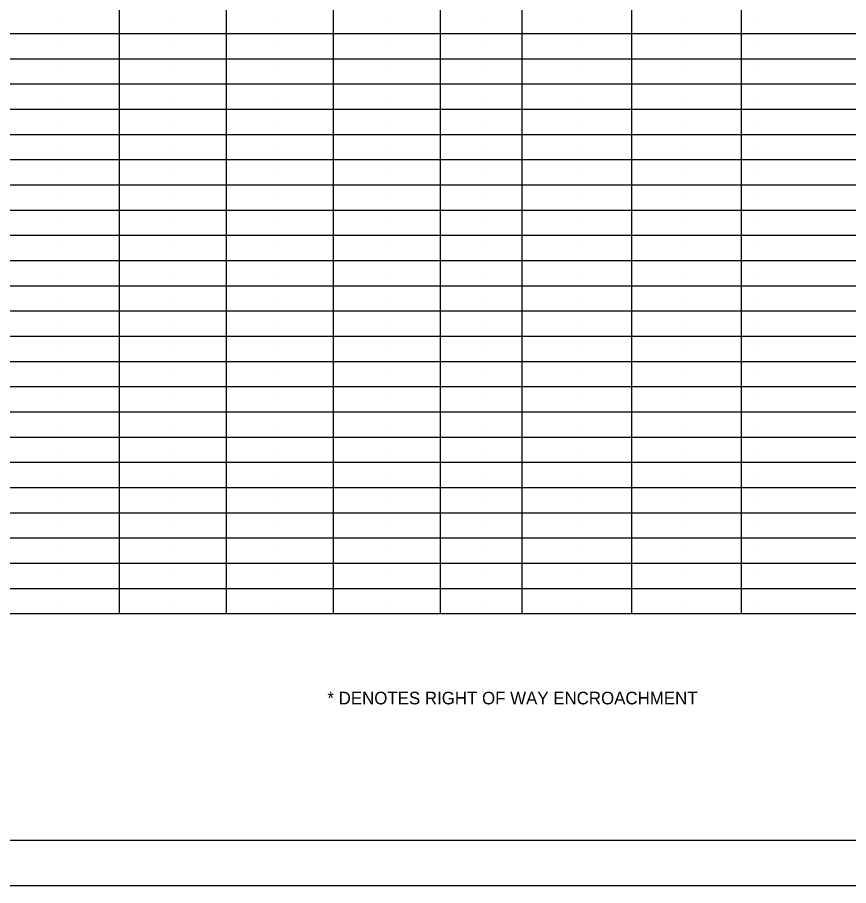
# Model space of a CAD drawing. Extents: x 0 to 34, y 0 to 22.
# Drawn here: x 15.55 to 24.77, y 0 to 9.64 of the extents above; entities that cross this region are included whole.
import ezdxf

# ---------------------------------------------------------------- set-up
doc = ezdxf.new("R2010")
doc.units = 0
for name, color, linetype in [('SC_Scratch1', 7, 'Continuous'), ('SH_Border', 7, 'Continuous'), ('SH_Cut_Line', 7, 'Continuous'), ('SH_Data', 7, 'Continuous')]:
    doc.layers.add(name, color=color, linetype=linetype)

msp = doc.modelspace()

# ---------------------------------------------------------------- linework, layer by layer
at = {"layer": 'SC_Scratch1'}
for p, q in [((16.0519, 9.6), (16.0519, 9.6)), ((17.2706, 9.6), (17.2706, 9.6)), ((18.4581, 9.6), (18.4581, 9.6)), ((19.6456, 9.6), (19.6456, 9.6)), ((20.6925, 9.6), (20.6925, 9.6)), ((21.7549, 9.6), (21.7549, 9.6)), ((22.9737, 9.6), (22.9737, 9.6)), ((23.723, 9.6), (23.723, 9.6)), ((16.0519, 9.32), (16.0519, 9.32)), ((17.2706, 9.32), (17.2706, 9.32)), ((18.4581, 9.32), (18.4581, 9.32)), ((19.6456, 9.32), (19.6456, 9.32)), ((20.6925, 9.32), (20.6925, 9.32)), ((21.7549, 9.32), (21.7549, 9.32)), ((22.9737, 9.32), (22.9737, 9.32)), ((23.723, 9.32), (23.723, 9.32)), ((16.0519, 9.04), (16.0519, 9.04)), ((17.2706, 9.04), (17.2706, 9.04)), ((18.4581, 9.04), (18.4581, 9.04)), ((19.6456, 9.04), (19.6456, 9.04)), ((20.6925, 9.04), (20.6925, 9.04)), ((21.7549, 9.04), (21.7549, 9.04)), ((22.9737, 9.04), (22.9737, 9.04)), ((23.723, 9.04), (23.723, 9.04)), ((16.0519, 8.76), (16.0519, 8.76)), ((17.2706, 8.76), (17.2706, 8.76)), ((18.4581, 8.76), (18.4581, 8.76)), ((19.6456, 8.76), (19.6456, 8.76)), ((20.6925, 8.76), (20.6925, 8.76)), ((21.7549, 8.76), (21.7549, 8.76)), ((22.9737, 8.76), (22.9737, 8.76)), ((23.723, 8.76), (23.723, 8.76)), ((16.0519, 8.48), (16.0519, 8.48)), ((17.2706, 8.48), (17.2706, 8.48)), ((18.4581, 8.48), (18.4581, 8.48)), ((19.6456, 8.48), (19.6456, 8.48)), ((20.6925, 8.48), (20.6925, 8.48)), ((21.7549, 8.48), (21.7549, 8.48)), ((22.9737, 8.48), (22.9737, 8.48)), ((23.723, 8.48), (23.723, 8.48)), ((16.0519, 8.2), (16.0519, 8.2)), ((17.2706, 8.2), (17.2706, 8.2)), ((18.4581, 8.2), (18.4581, 8.2)), ((19.6456, 8.2), (19.6456, 8.2)), ((20.6925, 8.2), (20.6925, 8.2)), ((21.7549, 8.2), (21.7549, 8.2)), ((22.9737, 8.2), (22.9737, 8.2)), ((23.723, 8.2), (23.723, 8.2)), ((16.0519, 7.92), (16.0519, 7.92)), ((17.2706, 7.92), (17.2706, 7.92)), ((18.4581, 7.92), (18.4581, 7.92)), ((19.6456, 7.92), (19.6456, 7.92)), ((20.6925, 7.92), (20.6925, 7.92)), ((21.7549, 7.92), (21.7549, 7.92)), ((22.9737, 7.92), (22.9737, 7.92)), ((23.723, 7.92), (23.723, 7.92)), ((16.0519, 7.64), (16.0519, 7.64)), ((17.2706, 7.64), (17.2706, 7.64)), ((18.4581, 7.64), (18.4581, 7.64)), ((19.6456, 7.64), (19.6456, 7.64)), ((20.6925, 7.64), (20.6925, 7.64)), ((21.7549, 7.64), (21.7549, 7.64)), ((22.9737, 7.64), (22.9737, 7.64)), ((23.723, 7.64), (23.723, 7.64)), ((16.0519, 7.36), (16.0519, 7.36)), ((17.2706, 7.36), (17.2706, 7.36)), ((18.4581, 7.36), (18.4581, 7.36)), ((19.6456, 7.36), (19.6456, 7.36)), ((20.6925, 7.36), (20.6925, 7.36)), ((21.7549, 7.36), (21.7549, 7.36)), ((22.9737, 7.36), (22.9737, 7.36)), ((23.723, 7.36), (23.723, 7.36)), ((16.0519, 7.08), (16.0519, 7.08)), ((17.2706, 7.08), (17.2706, 7.08)), ((18.4581, 7.08), (18.4581, 7.08)), ((19.6456, 7.08), (19.6456, 7.08)), ((20.6925, 7.08), (20.6925, 7.08)), ((21.7549, 7.08), (21.7549, 7.08)), ((22.9737, 7.08), (22.9737, 7.08)), ((23.723, 7.08), (23.723, 7.08)), ((16.0519, 6.8), (16.0519, 6.8)), ((17.2706, 6.8), (17.2706, 6.8)), ((18.4581, 6.8), (18.4581, 6.8)), ((19.6456, 6.8), (19.6456, 6.8)), ((20.6925, 6.8), (20.6925, 6.8)), ((21.7549, 6.8), (21.7549, 6.8)), ((22.9737, 6.8), (22.9737, 6.8)), ((23.723, 6.8), (23.723, 6.8)), ((16.0519, 6.52), (16.0519, 6.52)), ((17.2706, 6.52), (17.2706, 6.52)), ((18.4581, 6.52), (18.4581, 6.52)), ((19.6456, 6.52), (19.6456, 6.52)), ((20.6925, 6.52), (20.6925, 6.52)), ((21.7549, 6.52), (21.7549, 6.52)), ((22.9737, 6.52), (22.9737, 6.52)), ((23.723, 6.52), (23.723, 6.52)), ((16.0519, 6.24), (16.0519, 6.24)), ((17.2706, 6.24), (17.2706, 6.24)), ((18.4581, 6.24), (18.4581, 6.24)), ((19.6456, 6.24), (19.6456, 6.24)), ((20.6925, 6.24), (20.6925, 6.24)), ((21.7549, 6.24), (21.7549, 6.24)), ((22.9737, 6.24), (22.9737, 6.24)), ((23.723, 6.24), (23.723, 6.24)), ((16.0519, 5.96), (16.0519, 5.96)), ((17.2706, 5.96), (17.2706, 5.96)), ((18.4581, 5.96), (18.4581, 5.96)), ((19.6456, 5.96), (19.6456, 5.96)), ((20.6925, 5.96), (20.6925, 5.96)), ((21.7549, 5.96), (21.7549, 5.96)), ((22.9737, 5.96), (22.9737, 5.96)), ((23.723, 5.96), (23.723, 5.96)), ((16.0519, 5.68), (16.0519, 5.68)), ((17.2706, 5.68), (17.2706, 5.68)), ((18.4581, 5.68), (18.4581, 5.68)), ((19.6456, 5.68), (19.6456, 5.68)), ((20.6925, 5.68), (20.6925, 5.68)), ((21.7549, 5.68), (21.7549, 5.68)), ((22.9737, 5.68), (22.9737, 5.68)), ((23.723, 5.68), (23.723, 5.68)), ((16.0519, 5.4), (16.0519, 5.4)), ((17.2706, 5.4), (17.2706, 5.4)), ((18.4581, 5.4), (18.4581, 5.4)), ((19.6456, 5.4), (19.6456, 5.4)), ((20.6925, 5.4), (20.6925, 5.4)), ((21.7549, 5.4), (21.7549, 5.4)), ((22.9737, 5.4), (22.9737, 5.4)), ((23.723, 5.4), (23.723, 5.4)), ((16.0519, 5.12), (16.0519, 5.12)), ((17.2706, 5.12), (17.2706, 5.12)), ((18.4581, 5.12), (18.4581, 5.12)), ((19.6456, 5.12), (19.6456, 5.12)), ((20.6925, 5.12), (20.6925, 5.12)), ((21.7549, 5.12), (21.7549, 5.12)), ((22.9737, 5.12), (22.9737, 5.12)), ((23.723, 5.12), (23.723, 5.12)), ((16.0519, 4.84), (16.0519, 4.84)), ((17.2706, 4.84), (17.2706, 4.84)), ((18.4581, 4.84), (18.4581, 4.84)), ((19.6456, 4.84), (19.6456, 4.84)), ((20.6925, 4.84), (20.6925, 4.84)), ((21.7549, 4.84), (21.7549, 4.84)), ((22.9737, 4.84), (22.9737, 4.84)), ((23.723, 4.84), (23.723, 4.84)), ((16.0519, 4.56), (16.0519, 4.56)), ((17.2706, 4.56), (17.2706, 4.56)), ((18.4581, 4.56), (18.4581, 4.56)), ((19.6456, 4.56), (19.6456, 4.56)), ((20.6925, 4.56), (20.6925, 4.56)), ((21.7549, 4.56), (21.7549, 4.56)), ((22.9737, 4.56), (22.9737, 4.56)), ((23.723, 4.56), (23.723, 4.56)), ((16.0519, 4.28), (16.0519, 4.28)), ((17.2706, 4.28), (17.2706, 4.28)), ((18.4581, 4.28), (18.4581, 4.28)), ((19.6456, 4.28), (19.6456, 4.28)), ((20.6925, 4.28), (20.6925, 4.28)), ((21.7549, 4.28), (21.7549, 4.28)), ((22.9737, 4.28), (22.9737, 4.28)), ((23.723, 4.28), (23.723, 4.28)), ((16.0519, 4), (16.0519, 4)), ((17.2706, 4), (17.2706, 4)), ((18.4581, 4), (18.4581, 4)), ((19.6456, 4), (19.6456, 4)), ((20.6925, 4), (20.6925, 4)), ((21.7549, 4), (21.7549, 4)), ((22.9737, 4), (22.9737, 4)), ((23.723, 4), (23.723, 4)), ((16.0519, 3.72), (16.0519, 3.72)), ((17.2706, 3.72), (17.2706, 3.72)), ((18.4581, 3.72), (18.4581, 3.72)), ((19.6456, 3.72), (19.6456, 3.72)), ((20.6925, 3.72), (20.6925, 3.72)), ((21.7549, 3.72), (21.7549, 3.72)), ((22.9737, 3.72), (22.9737, 3.72)), ((23.723, 3.72), (23.723, 3.72)), ((16.0519, 3.44), (16.0519, 3.44)), ((17.2706, 3.44), (17.2706, 3.44)), ((18.4581, 3.44), (18.4581, 3.44)), ((19.6456, 3.44), (19.6456, 3.44)), ((20.6925, 3.44), (20.6925, 3.44)), ((21.7549, 3.44), (21.7549, 3.44)), ((22.9737, 3.44), (22.9737, 3.44)), ((23.723, 3.44), (23.723, 3.44)), ((16.0519, 3.16), (16.0519, 3.16)), ((17.2706, 3.16), (17.2706, 3.16)), ((18.4581, 3.16), (18.4581, 3.16)), ((19.6456, 3.16), (19.6456, 3.16)), ((20.6925, 3.16), (20.6925, 3.16)), ((21.7549, 3.16), (21.7549, 3.16)), ((22.9737, 3.16), (22.9737, 3.16)), ((23.723, 3.16), (23.723, 3.16))]:
    msp.add_line(p, q, dxfattribs=at)
at = {"layer": 'SH_Border'}
msp.add_lwpolyline([(1.5, 21.5), (33.5, 21.5), (33.5, 0.5), (1.5, 0.5)], close=True, dxfattribs=at)
at = {"layer": 'SH_Cut_Line'}
msp.add_lwpolyline([(0, 0), (34, 0), (34, 22), (0, 22)], close=True, dxfattribs=at)
at = {"layer": 'SH_Data'}
for p, q in [((16.6769, 19.86), (16.6769, 3.02)), ((17.8644, 19.86), (17.8644, 3.02)), ((19.0519, 19.86), (19.0519, 3.02)), ((20.2394, 19.86), (20.2394, 3.02)), ((21.1455, 19.86), (21.1455, 3.02)), ((23.583, 19.86), (23.583, 3.02)), ((22.3643, 19.56), (22.3643, 3.02)), ((1.5, 9.46), (32, 9.46)), ((1.5, 9.18), (32, 9.18)), ((1.5, 8.9), (32, 8.9)), ((1.5, 8.62), (32, 8.62)), ((1.5, 8.34), (32, 8.34)), ((1.5, 8.06), (32, 8.06)), ((1.5, 7.78), (32, 7.78)), ((1.5, 7.5), (32, 7.5)), ((1.5, 7.22), (32, 7.22)), ((1.5, 6.94), (32, 6.94)), ((1.5, 6.66), (32, 6.66)), ((1.5, 6.38), (32, 6.38)), ((1.5, 6.1), (32, 6.1)), ((1.5, 5.82), (32, 5.82)), ((1.5, 5.54), (32, 5.54)), ((1.5, 5.26), (32, 5.26)), ((1.5, 4.98), (32, 4.98)), ((1.5, 4.7), (32, 4.7)), ((1.5, 4.42), (32, 4.42)), ((1.5, 4.14), (32, 4.14)), ((1.5, 3.86), (32, 3.86)), ((1.5, 3.58), (32, 3.58)), ((1.5, 3.3), (32, 3.3)), ((1.5, 3.02), (32, 3.02))]:
    msp.add_line(p, q, dxfattribs=at)

# ---------------------------------------------------------------- texts
msp.add_text('* DENOTES RIGHT OF WAY ENCROACHMENT', height=0.14, dxfattribs=at).set_placement((18.9894, 2.0125))

doc.saveas('drawing.dxf')
